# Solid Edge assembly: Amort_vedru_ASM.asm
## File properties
Author: KULL
Template: Iso Metric Assembly.asm
Last saved by: KULL
Revision: 1
Application: Solid Edge
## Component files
Suspension1.par
vedru.par
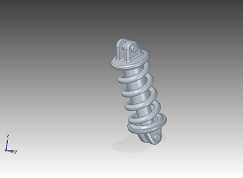
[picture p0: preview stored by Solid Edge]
